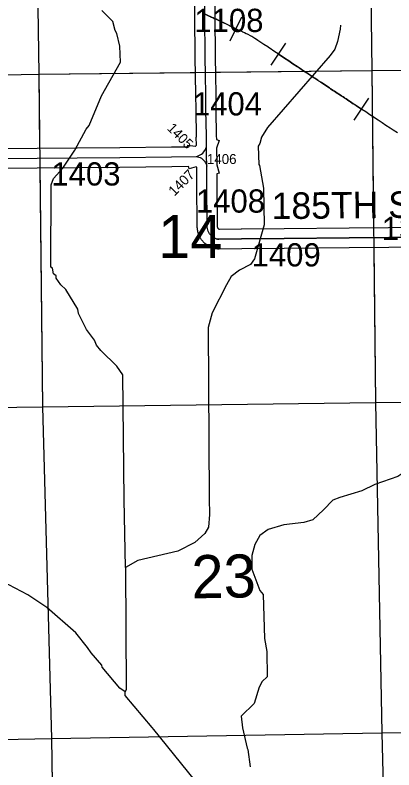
# Model space of a CAD drawing. Extents: x 23.6 to 68.7, y -63 to -29.
# Drawn here: x 42.522 to 43.662, y -43.727 to -41.451 of the extents above; entities that cross this region are included whole.
import ezdxf

# ---------------------------------------------------------------- set-up
doc = ezdxf.new("R2010")
doc.units = 0
for name, color, linetype in [('tdCoHydroRiver', 7, 'Continuous'), ('tdCoPipe', 7, 'Continuous'), ('tdCoSecRdNmbr', 7, 'Continuous'), ('tdCoSecRdTxt', 7, 'Continuous'), ('tdCoSecRteBand', 7, 'Continuous'), ('tdCoSecRteCL', 7, 'Continuous'), ('tdCoSectLine', 7, 'Continuous'), ('tdCoSectLinePart', 7, 'Continuous'), ('tdCoSectNmbr', 7, 'Continuous'), ('tdCoSurfGravel', 7, 'Continuous')]:
    doc.layers.add(name, color=color, linetype=linetype)

msp = doc.modelspace()

# ---------------------------------------------------------------- linework, layer by layer
at = {"layer": 'tdCoHydroRiver'}
for points in [[(42.8499, -42.9112), (42.8458, -42.5359), (42.8281, -42.5091), (42.7802, -42.4619), (42.7674, -42.4462), (42.7609, -42.4304), (42.7369, -42.3989), (42.7128, -42.3502), (42.7111, -42.3376), (42.6742, -42.278), (42.6599, -42.2639), (42.6454, -42.2435), (42.6454, -42.2372), (42.6374, -42.231), (42.6341, -42.2136), (42.6294, -42.2105), (42.6302, -41.9627), (42.6379, -41.9437), (42.666, -41.9118), (42.7018, -41.8578), (42.7359, -41.7944), (42.7453, -41.7832), (42.7823, -41.6945), (42.8397, -41.5929), (42.8377, -41.544), (42.8279, -41.5062), (42.8231, -41.4968), (42.8165, -41.47), (42.783, -41.4372)], [(43.5017, -41.4808), (43.5002, -41.4935), (43.4926, -41.5299), (43.485, -41.5536), (43.471, -41.5727), (43.282, -41.7892), (43.2634, -41.8193), (43.2588, -41.8383), (43.2541, -41.8463), (43.2562, -41.9015), (43.2578, -41.9046), (43.2695, -41.9724), (43.2722, -42.0829), (43.2432, -42.1857), (43.2307, -42.2032), (43.1977, -42.2194), (43.1726, -42.2386), (43.1587, -42.264), (43.1153, -42.3483), (43.1031, -42.3926), (43.1064, -42.9079)], [(43.7132, -42.8158), (43.674, -42.8415), (43.6048, -42.8658), (43.5655, -42.8851), (43.4994, -42.9053)], [(42.853, -43.4908), (42.8372, -43.4799), (42.7845, -43.4172), (42.7828, -43.4109), (42.7509, -43.3733), (42.7397, -43.3577), (42.7046, -43.3138), (42.617, -43.2373), (42.5598, -43.1984), (42.5027, -43.1689), (42.3349, -43.1153), (41.7, -42.9202)], [(42.8542, -43.1166), (42.8499, -42.9112)], [(43.1064, -42.9079), (43.1068, -42.957), (43.1041, -42.9949), (43.0932, -43.0141), (43.0634, -43.0413), (43.0116, -43.0672), (42.8919, -43.0956), (42.8542, -43.1166)], [(43.4994, -42.9053), (43.479, -42.9134), (43.4508, -42.9421), (43.418, -42.9724), (43.3912, -42.9805), (43.3313, -42.9874), (43.2841, -43.0021), (43.259, -43.0197), (43.2435, -43.0466), (43.2343, -43.0799), (43.2347, -43.1209), (43.259, -43.1854), (43.2686, -43.1979), (43.273, -43.3305), (43.2797, -43.3699), (43.2804, -43.4457), (43.2663, -43.46), (43.257, -43.4775), (43.2417, -43.5265), (43.2026, -43.5648), (43.2061, -43.5995), (43.2209, -43.6609), (43.2225, -43.6656), (43.2293, -43.7176)], [(42.8542, -43.1166), (42.8561, -43.4844), (42.853, -43.4908)], [(43.2254, -43.9687), (43.2237, -43.9592), (43.2078, -43.9436), (43.2077, -43.9389), (43.1885, -43.9138), (42.9394, -43.6052), (42.9346, -43.5989), (42.8531, -43.5018), (42.853, -43.4908)]]:
    msp.add_lwpolyline(points, dxfattribs=at)
at = {"layer": 'tdCoPipe'}
for p, q in [((43.169, -41.5279), (43.2041, -41.4558)), ((43.2929, -41.6018), (43.3374, -41.5351)), ((43.5429, -41.7678), (43.5873, -41.701))]:
    msp.add_line(p, q, dxfattribs=at)
for points in [[(43.0945, -41.4479), (43.1067, -41.4536), (43.1084, -41.4544), (43.1128, -41.4565), (43.1179, -41.459), (43.1212, -41.4605), (43.1273, -41.4634), (43.1319, -41.4655), (43.1429, -41.4707), (43.1454, -41.4719), (43.1485, -41.4734), (43.159, -41.4784), (43.1724, -41.485), (43.1757, -41.4865), (43.1812, -41.4892), (43.1829, -41.49), (43.1866, -41.4918)], [(43.673, -41.8062), (43.6605, -41.7978), (43.6509, -41.7915), (43.6384, -41.7832), (43.6274, -41.7758), (43.6151, -41.7676), (43.6044, -41.7605), (43.6027, -41.7593), (43.5902, -41.751), (43.5822, -41.7457), (43.5776, -41.7427), (43.5663, -41.7353), (43.5651, -41.7345), (43.5556, -41.7282), (43.5526, -41.7262), (43.5443, -41.7207), (43.5402, -41.7179), (43.5321, -41.7125), (43.5292, -41.7106), (43.5278, -41.7096), (43.5265, -41.7088), (43.5231, -41.7066), (43.5187, -41.7037), (43.5152, -41.7014), (43.5138, -41.7005), (43.5094, -41.6975), (43.5058, -41.6951), (43.5045, -41.6943), (43.4963, -41.6889), (43.4933, -41.6869), (43.492, -41.6861), (43.4874, -41.683), (43.4833, -41.6803), (43.4808, -41.6786), (43.4793, -41.6777), (43.4717, -41.6726), (43.4683, -41.6703), (43.4579, -41.6634), (43.45, -41.6582), (43.4454, -41.6551), (43.4425, -41.6531), (43.4356, -41.6486), (43.433, -41.6468), (43.4245, -41.6412), (43.4206, -41.6386), (43.4134, -41.6339), (43.4081, -41.6304), (43.4006, -41.6253), (43.3956, -41.6221), (43.3932, -41.6205), (43.3885, -41.6174), (43.3831, -41.6138), (43.3719, -41.6063), (43.3708, -41.6055), (43.3583, -41.5972), (43.354, -41.5943), (43.3459, -41.5889), (43.3334, -41.5806), (43.3263, -41.576), (43.3209, -41.5724), (43.3143, -41.568), (43.3085, -41.5641), (43.2982, -41.5573), (43.2959, -41.5559), (43.2911, -41.5527), (43.2834, -41.5476), (43.2824, -41.5468), (43.271, -41.5393), (43.2585, -41.5311), (43.2528, -41.5272), (43.246, -41.5228), (43.2439, -41.5214), (43.2345, -41.5152), (43.2324, -41.5139), (43.2214, -41.5086), (43.218, -41.507), (43.2123, -41.5043), (43.2079, -41.5022), (43.2046, -41.5006), (43.1945, -41.4958), (43.1828, -41.4901), (43.1811, -41.4893), (43.1757, -41.4866), (43.1724, -41.4851), (43.1589, -41.4785), (43.1485, -41.4734), (43.1454, -41.472), (43.1429, -41.4707), (43.1319, -41.4656), (43.1272, -41.4634), (43.1212, -41.4606), (43.1179, -41.459), (43.1128, -41.4566), (43.1084, -41.4545), (43.1066, -41.4537), (43.0945, -41.448)], [(43.3151, -41.5685), (43.3209, -41.5723), (43.3263, -41.5759), (43.3334, -41.5806), (43.3459, -41.5889), (43.354, -41.5943), (43.3584, -41.5972), (43.3708, -41.6055), (43.372, -41.6062), (43.3832, -41.6137), (43.3886, -41.6173), (43.3933, -41.6204), (43.3956, -41.622), (43.4006, -41.6253), (43.4081, -41.6303), (43.4135, -41.6338), (43.4206, -41.6385), (43.4245, -41.6411), (43.433, -41.6467), (43.4357, -41.6486), (43.4425, -41.6531), (43.4454, -41.6551), (43.4501, -41.6581), (43.4579, -41.6633), (43.4684, -41.6703), (43.4718, -41.6726), (43.4793, -41.6776), (43.4808, -41.6786), (43.4833, -41.6802), (43.4875, -41.683), (43.4921, -41.686), (43.4933, -41.6869), (43.4963, -41.6888), (43.5046, -41.6943), (43.5059, -41.6951), (43.5094, -41.6975), (43.5139, -41.7004), (43.5153, -41.7014), (43.5187, -41.7036), (43.5232, -41.7065), (43.5265, -41.7088), (43.5278, -41.7096), (43.5292, -41.7105), (43.5322, -41.7125), (43.5402, -41.7178), (43.5444, -41.7206), (43.5527, -41.7261), (43.5557, -41.7281), (43.5651, -41.7344)]]:
    msp.add_lwpolyline(points, dxfattribs=at)
at = {"layer": 'tdCoSecRteBand'}
for points in [[(42.4503, -41.8531), (42.5879, -41.8519), (42.5879, -41.8519), (42.588, -41.8519), (42.7089, -41.851), (42.8371, -41.8498), (42.993, -41.8482), (43.0414, -41.8476), (43.0421, -41.843), (43.0642, -41.8464), (43.0651, -41.8459), (43.066, -41.8451), (43.0668, -41.8442), (43.0676, -41.8432), (43.068, -41.8425), (43.0674, -41.8183), (43.0679, -41.8183), (43.0678, -41.8145), (43.0667, -41.739), (43.0667, -41.739), (43.0667, -41.739), (43.0659, -41.6867), (43.0659, -41.6866), (43.0659, -41.6865), (43.0655, -41.6365), (43.0645, -41.5734), (43.0645, -41.5734), (43.0645, -41.5734), (43.063, -41.4582), (43.0618, -41.3779)], [(43.1218, -41.3771), (43.123, -41.4574), (43.123, -41.4574), (43.123, -41.4574), (43.1245, -41.5725), (43.1255, -41.6357), (43.1255, -41.6358), (43.1255, -41.636), (43.1259, -41.6859), (43.1267, -41.7381), (43.1278, -41.8137), (43.1278, -41.8139), (43.1278, -41.814), (43.1279, -41.8258), (43.1359, -41.8285), (43.1282, -41.8521), (43.1286, -41.8713), (43.1286, -41.8714), (43.1286, -41.8714), (43.1287, -41.876), (43.1291, -41.876), (43.1292, -41.9021), (43.136, -41.9273), (43.1297, -41.929), (43.1298, -41.9356), (43.1294, -41.9356), (43.1296, -41.9975), (43.13, -42.0489), (43.1305, -42.0881), (43.1307, -42.0893), (43.1309, -42.0903), (43.1312, -42.0912), (43.1316, -42.092), (43.1321, -42.0929), (43.1327, -42.0936), (43.1334, -42.0943), (43.1341, -42.095), (43.1349, -42.0955), (43.1358, -42.0959), (43.1367, -42.0963), (43.1376, -42.0965), (43.203, -42.0951), (43.2033, -42.095), (43.2035, -42.095), (43.3317, -42.0943), (43.5274, -42.0923), (43.5275, -42.0923), (43.5275, -42.0923), (43.6466, -42.0914), (43.7567, -42.0904)], [(43.7571, -42.1504), (43.6471, -42.1514), (43.6471, -42.1514), (43.6471, -42.1514), (43.528, -42.1523), (43.3322, -42.1543), (43.3321, -42.1543), (43.3321, -42.1543), (43.2042, -42.155), (43.1363, -42.1566), (43.1337, -42.1567), (43.1311, -42.1563), (43.1269, -42.1556), (43.1253, -42.1554), (43.1237, -42.1549), (43.1196, -42.1538), (43.118, -42.1534), (43.1165, -42.1528), (43.1125, -42.1513), (43.111, -42.1507), (43.1096, -42.1499), (43.1058, -42.148), (43.1043, -42.1472), (43.103, -42.1463), (43.0994, -42.144), (43.0981, -42.1431), (43.0968, -42.142), (43.0935, -42.1393), (43.0923, -42.1382), (43.0912, -42.137), (43.0882, -42.134), (43.0871, -42.1328), (43.0861, -42.1315), (43.0835, -42.1281), (43.0825, -42.1268), (43.0816, -42.1254), (43.0794, -42.1218), (43.0786, -42.1204), (43.0779, -42.1189), (43.0761, -42.115), (43.0754, -42.1135), (43.0749, -42.112), (43.0735, -42.108), (43.073, -42.1064), (43.0726, -42.1048), (43.0717, -42.1006), (43.0714, -42.099), (43.0712, -42.0974), (43.0707, -42.0932), (43.0706, -42.0918), (43.0706, -42.0904), (43.07, -42.0497), (43.07, -42.0496), (43.07, -42.0495), (43.0696, -41.9979), (43.0696, -41.9978), (43.0696, -41.9977), (43.0694, -41.9311), (43.0693, -41.9107), (43.069, -41.9102), (43.0686, -41.9096), (43.0681, -41.909), (43.0675, -41.9085), (43.0673, -41.9083), (43.0462, -41.9141), (43.0443, -41.9075), (42.9937, -41.9082), (42.9937, -41.9082), (42.9936, -41.9082), (42.8377, -41.9098), (42.8377, -41.9098), (42.8377, -41.9098), (42.7094, -41.911), (42.7094, -41.911), (42.7094, -41.911), (42.5884, -41.9119), (42.4509, -41.9131)]]:
    msp.add_lwpolyline(points, dxfattribs=at)
at = {"layer": 'tdCoSecRteCL'}
for points in [[(43.0981, -41.8476), (43.0978, -41.8142), (43.0967, -41.7386), (43.0959, -41.6862), (43.0955, -41.6362), (43.0945, -41.573), (43.093, -41.4578), (43.0918, -41.3775), (43.0909, -41.2947), (43.0891, -41.1801), (43.0885, -41.1419), (43.0884, -41.125)], [(43.0671, -41.8772), (43.0714, -41.876), (43.0756, -41.8744), (43.0796, -41.8723), (43.0833, -41.8697), (43.0867, -41.8668), (43.0898, -41.8635), (43.0925, -41.8599), (43.0948, -41.856), (43.0967, -41.8519), (43.0981, -41.8476)], [(43.0993, -41.9061), (43.0986, -41.872), (43.0981, -41.8476)], [(42.1597, -41.8862), (42.1819, -41.8859), (42.335, -41.885), (42.4506, -41.8831), (42.5882, -41.8819), (42.7091, -41.881), (42.8374, -41.8798), (42.9933, -41.8782), (43.0671, -41.8772)], [(43.0671, -41.8772), (43.0712, -41.8779), (43.0753, -41.879), (43.0792, -41.8806), (43.0829, -41.8826), (43.0863, -41.885), (43.0894, -41.8879), (43.0922, -41.891), (43.0946, -41.8945), (43.0966, -41.8982), (43.0982, -41.9021), (43.0993, -41.9061)], [(43.8549, -42.12), (43.757, -42.1204), (43.6468, -42.1214), (43.5277, -42.1223), (43.3319, -42.1243), (43.2037, -42.125), (43.1357, -42.1266), (43.1315, -42.126), (43.1273, -42.1249), (43.1234, -42.1233), (43.1196, -42.1214), (43.1161, -42.119), (43.1128, -42.1163), (43.1099, -42.1132), (43.1073, -42.1098), (43.1051, -42.1062), (43.1033, -42.1023), (43.1019, -42.0983), (43.101, -42.0942), (43.1006, -42.0899), (43.1, -42.0492), (43.0996, -41.9976), (43.0994, -41.9309), (43.0993, -41.9061)]]:
    msp.add_lwpolyline(points, dxfattribs=at)
at = {"layer": 'tdCoSectLine'}
for points in [[(43.5832, -40.6119), (43.5959, -41.6176)], [(42.5785, -40.6268), (42.5932, -41.629)], [(42.5932, -41.629), (43.5959, -41.6176)], [(43.5959, -41.6176), (44.6006, -41.6086)], [(43.5959, -41.6176), (43.6067, -42.6188)], [(41.5896, -41.6477), (42.5932, -41.629)], [(42.5932, -41.629), (42.6048, -42.6317)], [(42.6048, -42.6317), (43.6067, -42.6188)], [(43.6067, -42.6188), (44.6126, -42.6121)], [(43.6067, -42.6188), (43.6261, -43.6144)], [(41.5996, -42.6451), (42.6048, -42.6317)], [(42.6048, -42.6317), (42.6312, -43.6316)], [(42.6312, -43.6316), (43.6261, -43.6144)], [(43.6261, -43.6144), (44.6289, -43.6086)], [(43.6261, -43.6144), (43.6508, -44.6219)], [(41.628, -43.652), (42.6312, -43.6316)], [(42.6312, -43.6316), (42.6467, -44.6366)]]:
    msp.add_lwpolyline(points, dxfattribs=at)
at = {"layer": 'tdCoSectLinePart'}
for points in [[(42.5864, -41.1607), (42.5932, -41.629)], [(43.59, -41.1502), (43.5959, -41.6176)], [(42.5932, -41.629), (43.0649, -41.6237)], [(43.1249, -41.623), (43.5959, -41.6176)], [(43.5959, -41.6176), (43.8162, -41.6157)], [(43.5959, -41.6176), (43.601, -42.092)], [(41.5896, -41.6477), (42.5932, -41.629)], [(42.5932, -41.629), (42.5958, -41.8519)], [(42.5965, -41.9119), (42.6048, -42.6317)], [(43.6017, -42.152), (43.6067, -42.6188)], [(42.6048, -42.6317), (43.6067, -42.6188)], [(43.6067, -42.6188), (44.5825, -42.6123)], [(43.6067, -42.6188), (43.6261, -43.6144)], [(41.5996, -42.6451), (42.6048, -42.6317)], [(42.6048, -42.6317), (42.6312, -43.6316)], [(42.6312, -43.6316), (43.6261, -43.6144)], [(43.6261, -43.6144), (43.8453, -43.6131)], [(43.6261, -43.6144), (43.6508, -44.6219)], [(41.628, -43.652), (42.6312, -43.6316)], [(42.6312, -43.6316), (42.6385, -44.1067)]]:
    msp.add_lwpolyline(points, dxfattribs=at)
at = {"layer": 'tdCoSurfGravel'}
for points in [[(43.0955, -41.6362), (43.0945, -41.573), (43.093, -41.4578), (43.0918, -41.3775), (43.0909, -41.2947), (43.0891, -41.1801), (43.0885, -41.1419), (43.0884, -41.125), (43.0881, -41.0878), (43.0872, -41.0124), (43.0854, -40.9307), (43.085, -40.8774), (43.0837, -40.8012), (43.0829, -40.7143), (43.0819, -40.6734), (43.0812, -40.6232), (43.0793, -40.5916)], [(43.0993, -41.9061), (43.0986, -41.872), (43.0981, -41.8476), (43.0978, -41.8142), (43.0967, -41.7386), (43.0959, -41.6862), (43.0955, -41.6362)], [(43.0671, -41.8772), (43.0714, -41.876), (43.0756, -41.8744), (43.0796, -41.8723), (43.0833, -41.8697), (43.0867, -41.8668), (43.0898, -41.8635), (43.0925, -41.8599), (43.0948, -41.856), (43.0967, -41.8519), (43.0981, -41.8476)], [(42.4506, -41.8831), (42.5882, -41.8819), (42.7091, -41.881), (42.8374, -41.8798), (42.9933, -41.8782), (43.0671, -41.8772), (43.0712, -41.8779), (43.0753, -41.879), (43.0792, -41.8806), (43.0829, -41.8826), (43.0863, -41.885), (43.0894, -41.8879), (43.0922, -41.891), (43.0946, -41.8945), (43.0966, -41.8982), (43.0982, -41.9021), (43.0993, -41.9061)], [(43.1234, -42.1233), (43.1196, -42.1214), (43.1161, -42.119), (43.1128, -42.1163), (43.1099, -42.1132), (43.1073, -42.1098), (43.1051, -42.1062), (43.1033, -42.1023), (43.1019, -42.0983), (43.101, -42.0942), (43.1006, -42.0899), (43.1, -42.0492), (43.0996, -41.9976), (43.0994, -41.9309), (43.0993, -41.9061)], [(43.1234, -42.1233), (43.1273, -42.1249), (43.1315, -42.126), (43.1357, -42.1266), (43.2037, -42.125), (43.3319, -42.1243), (43.5277, -42.1223), (43.6468, -42.1214), (43.757, -42.1204), (43.8549, -42.12)]]:
    msp.add_lwpolyline(points, dxfattribs=at)

# ---------------------------------------------------------------- texts
at = {"layer": 'tdCoSecRdNmbr'}
for s, height, rotation, p in [('1108', 0.07, 0.0336, (43.0616, -41.5018)), ('1404', 0.07, 0.0336, (43.0572, -41.7534)), ('1405', 0.03, 315.0327, (42.9773, -41.794)), ('1406', 0.03, 0.0336, (43.0994, -41.8998)), ('1403', 0.07, 0.0333, (42.6311, -41.9647)), ('1407', 0.03, 45.0322, (43.0017, -41.998)), ('1408', 0.07, 0.0337, (43.0663, -42.0464)), ('1305', 0.07, 0.034, (43.626, -42.129)), ('1409', 0.07, 0.0337, (43.2339, -42.2087))]:
    msp.add_text(s, height=height, rotation=rotation, dxfattribs=at).set_placement(p)
at = {"layer": 'tdCoSecRdTxt'}
msp.add_text('185TH ST', height=0.08, rotation=0.548, dxfattribs=at).set_placement((43.2948, -42.066))
at = {"layer": 'tdCoSectNmbr'}
for s, rotation, p in [('14', 0.0335, (42.9525, -42.1834)), ('23', 1.0336, (43.0542, -43.2096))]:
    msp.add_text(s, height=0.13, rotation=rotation, dxfattribs=at).set_placement(p)

doc.saveas('drawing.dxf')
